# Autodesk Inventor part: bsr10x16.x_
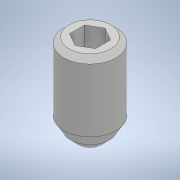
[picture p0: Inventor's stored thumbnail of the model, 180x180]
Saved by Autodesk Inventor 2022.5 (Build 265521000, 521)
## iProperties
Created: 2020-01
Part Number: bsr10x16.x_
Material: 一般
Document SubType Name: Modeling
Designer: ImaoCorp
Density: 1 g/cm^3
Appearance: 既定
Sending System: SOLIDWORKS 2018-2018316
MC: AMD64
MC_MODEL: Intel64 Family 6 Model 60 Stepping 3, GenuineIntel
OS: Windows_NT
FRU: Parasolid Version 30.0, build 310,  6- 8-2018
FORMAT: text
GUISE: transmit
KEY: bsr10x16
FILE: bsr10x16.x_t
DATE: Thu Jan 23 16:48:11 2020
Author: ImaoCorp
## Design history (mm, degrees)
feature "Base1"
node "ソリッド1"
